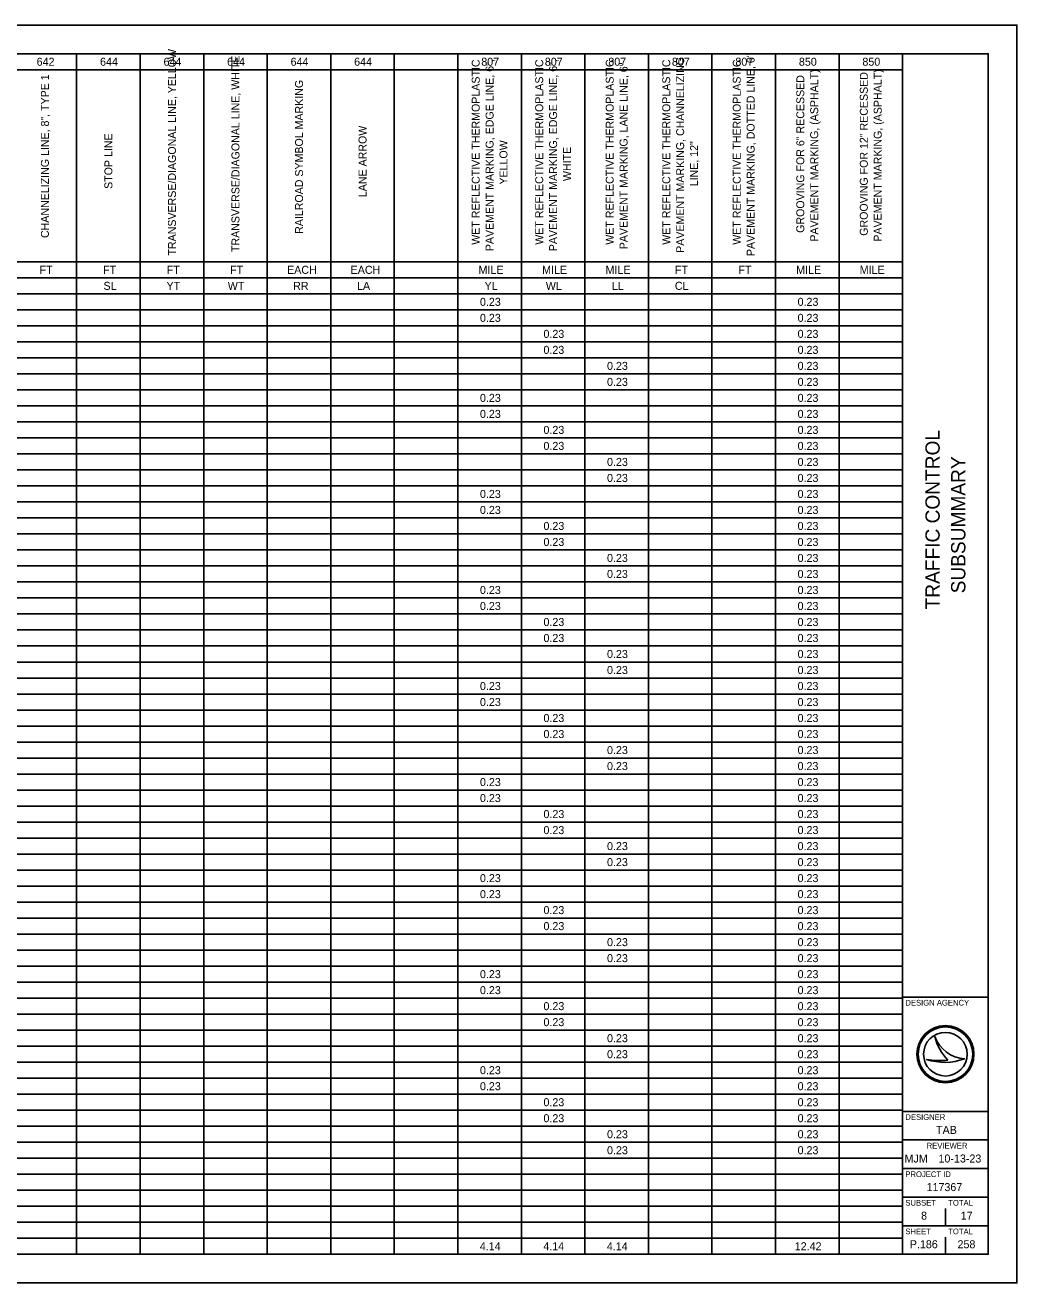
# Model space of a CAD drawing. Extents: x 0 to 34, y 0 to 22.
# Drawn here: x 16.65 to 34, y 0 to 22 of the extents above; entities that cross this region are included whole.
import ezdxf

# ---------------------------------------------------------------- set-up
doc = ezdxf.new("R2010")
doc.units = 0
for name, color, linetype in [('SH_Border', 7, 'Continuous'), ('SH_Cut_Line', 7, 'Continuous'), ('SH_Data', 7, 'Continuous'), ('SH_Text', 7, 'Continuous')]:
    doc.layers.add(name, color=color, linetype=linetype)

msp = doc.modelspace()

# ---------------------------------------------------------------- linework, layer by layer
at = {"layer": 'SH_Border'}
for p, q in [((32, 0.5), (32, 21.5)), ((32, 5), (33.5, 5)), ((32, 3), (33.5, 3)), ((32, 2.5), (33.5, 2.5)), ((32, 2), (33.5, 2)), ((32, 1.5), (33.5, 1.5)), ((32, 1), (33.5, 1))]:
    msp.add_line(p, q, dxfattribs=at)
msp.add_lwpolyline([(1.5, 21.5), (33.5, 21.5), (33.5, 0.5), (1.5, 0.5)], close=True, dxfattribs=at)
at = {"layer": 'SH_Cut_Line'}
msp.add_lwpolyline([(0, 0), (34, 0), (34, 22), (0, 22)], close=True, dxfattribs=at)
at = {"layer": 'SH_Data'}
for p, q in [((32.567, 4.31), (32.567, 4.31)), ((32.75, 4), (32.75, 4)), ((32.417, 3.91), (32.417, 3.91)), ((33.087, 3.919), (33.087, 3.919)), ((32.75, 1), (32.75, 1.3)), ((32.375, 0.675), (32.375, 0.675)), ((32.75, 0.5), (32.75, 0.8))]:
    msp.add_line(p, q, dxfattribs=at)
for radius in [0.5, 0.477, 0.477, 0.382]:
    msp.add_circle((32.75, 4), radius, dxfattribs=at)
for centre, radius, start, end in [((33.116, 4.498), 0.58, 198.9257, 198.9319), ((33.347, 4.47), 0.796, 191.6379, 191.6421), ((33.116, 4.498), 0.58, 198.9319, 267.1657), ((33.347, 4.47), 0.796, 191.6421, 226.0947), ((32.739, 4.87), 1.013, 251.4576, 290.0832), ((32.648, 5.154), 1.266, 259.4964, 259.4995), ((32.739, 4.87), 1.013, 251.4527, 251.4576), ((32.648, 5.154), 1.266, 259.4995, 276.6672)]:
    msp.add_arc(centre, radius, start, end, dxfattribs=at)
at = {"layer": 'SH_Text'}
for p, q in [((1.5, 21.5), (32, 21.5)), ((17.551, 21.5), (17.551, 0.5)), ((18.662, 21.5), (18.662, 0.5)), ((19.774, 21.5), (19.774, 0.5)), ((20.885, 21.5), (20.885, 0.5)), ((21.997, 21.5), (21.997, 0.5)), ((23.108, 21.5), (23.108, 0.5)), ((24.22, 21.5), (24.22, 0.5)), ((25.331, 21.5), (25.331, 0.5)), ((26.443, 21.5), (26.443, 0.5)), ((27.554, 21.5), (27.554, 0.5)), ((28.666, 21.5), (28.666, 0.5)), ((29.777, 21.5), (29.777, 0.5)), ((30.889, 21.5), (30.889, 0.5)), ((32, 21.5), (32, 0.5)), ((8.659, 21.22), (32, 21.22)), ((8.659, 17.86), (32, 17.86)), ((1.5, 17.58), (32, 17.58)), ((1.5, 17.3), (32, 17.3)), ((1.5, 17.02), (32, 17.02)), ((1.5, 16.74), (32, 16.74)), ((1.5, 16.46), (32, 16.46)), ((1.5, 16.18), (32, 16.18)), ((1.5, 15.9), (32, 15.9)), ((1.5, 15.62), (32, 15.62)), ((1.5, 15.34), (32, 15.34)), ((1.5, 15.06), (32, 15.06)), ((1.5, 14.78), (32, 14.78)), ((1.5, 14.5), (32, 14.5)), ((1.5, 14.22), (32, 14.22)), ((1.5, 13.94), (32, 13.94)), ((1.5, 13.66), (32, 13.66)), ((1.5, 13.38), (32, 13.38)), ((1.5, 13.1), (32, 13.1)), ((1.5, 12.82), (32, 12.82)), ((1.5, 12.54), (32, 12.54)), ((1.5, 12.26), (32, 12.26)), ((1.5, 11.98), (32, 11.98)), ((1.5, 11.7), (32, 11.7)), ((1.5, 11.42), (32, 11.42)), ((1.5, 11.14), (32, 11.14)), ((1.5, 10.86), (32, 10.86)), ((1.5, 10.58), (32, 10.58)), ((1.5, 10.3), (32, 10.3)), ((1.5, 10.02), (32, 10.02)), ((1.5, 9.74), (32, 9.74)), ((1.5, 9.46), (32, 9.46)), ((1.5, 9.18), (32, 9.18)), ((1.5, 8.9), (32, 8.9)), ((1.5, 8.62), (32, 8.62)), ((1.5, 8.34), (32, 8.34)), ((1.5, 8.06), (32, 8.06)), ((1.5, 7.78), (32, 7.78)), ((1.5, 7.5), (32, 7.5)), ((1.5, 7.22), (32, 7.22)), ((1.5, 6.94), (32, 6.94)), ((1.5, 6.66), (32, 6.66)), ((1.5, 6.38), (32, 6.38)), ((1.5, 6.1), (32, 6.1)), ((1.5, 5.82), (32, 5.82)), ((1.5, 5.54), (32, 5.54)), ((1.5, 5.26), (32, 5.26)), ((1.5, 4.98), (32, 4.98)), ((1.5, 4.7), (32, 4.7)), ((1.5, 4.42), (32, 4.42)), ((1.5, 4.14), (32, 4.14)), ((1.5, 3.86), (32, 3.86)), ((1.5, 3.58), (32, 3.58)), ((1.5, 3.3), (32, 3.3)), ((1.5, 3.02), (32, 3.02)), ((1.5, 2.74), (32, 2.74)), ((1.5, 2.46), (32, 2.46)), ((1.5, 2.18), (32, 2.18)), ((1.5, 1.9), (32, 1.9)), ((1.5, 1.62), (32, 1.62)), ((1.5, 1.34), (32, 1.34)), ((1.5, 1.06), (32, 1.06)), ((1.5, 0.78), (32, 0.78)), ((1.5, 0.5), (32, 0.5))]:
    msp.add_line(p, q, dxfattribs=at)

# ---------------------------------------------------------------- texts
at = {"layer": 'SH_Data'}
for s, p in [('TRAFFIC CONTROL', (32.65, 11.78)), ('SUBSUMMARY', (33.1, 12.061))]:
    msp.add_text(s, height=0.25, rotation=90, dxfattribs=at).set_placement(p)
for s, height, p in [('DESIGN AGENCY', 0.1, (32.05, 4.85)), ('DESIGNER', 0.1, (32.05, 2.85)), ('TAB', 0.14, (32.586, 2.605)), ('REVIEWER', 0.1, (32.422, 2.35)), ('MJM', 0.14, (32.035, 2.105)), ('10-13-23', 0.14, (32.629, 2.105)), ('PROJECT ID', 0.1, (32.05, 1.85)), ('117367', 0.14, (32.42, 1.605)), ('SUBSET', 0.1, (32.05, 1.35)), ('TOTAL', 0.1, (32.8, 1.35)), ('8', 0.14, (32.324, 1.105)), ('17', 0.14, (33.018, 1.105)), ('SHEET', 0.1, (32.05, 0.85)), ('TOTAL', 0.1, (32.8, 0.85)), ('P.186', 0.14, (32.127, 0.605)), ('258', 0.14, (32.962, 0.605))]:
    msp.add_text(s, height=height, dxfattribs=at).set_placement(p)
at = {"layer": 'SH_Text'}
for s, height, p in [('TRANSVERSE/DIAGONAL LINE, YELLOW', 0.13893, (19.288, 17.97)), ('TRANSVERSE/DIAGONAL LINE, WHITE', 0.13893, (20.399, 18.031)), ('WET REFLECTIVE THERMOPLASTIC ', 0.13893, (24.602, 18.159)), ('PAVEMENT MARKING, EDGE LINE, 6", ', 0.13893, (24.845, 18.046)), ('WET REFLECTIVE THERMOPLASTIC ', 0.13893, (25.713, 18.159)), ('PAVEMENT MARKING, EDGE LINE, 6", ', 0.13893, (25.956, 18.046)), ('WET REFLECTIVE THERMOPLASTIC ', 0.13893, (26.946, 18.159)), ('WET REFLECTIVE THERMOPLASTIC ', 0.13893, (27.936, 18.159)), ('PAVEMENT MARKING, CHANNELIZING ', 0.13893, (28.179, 18.017)), ('WET REFLECTIVE THERMOPLASTIC ', 0.13893, (29.169, 18.159)), ('PAVEMENT MARKING, DOTTED LINE, 6"', 0.13893, (29.412, 17.96)), ('CHANNELIZING LINE, 8", TYPE 1', 0.13893, (17.065, 18.276)), ('PAVEMENT MARKING, LANE LINE, 6"', 0.13893, (27.189, 18.08)), ('PAVEMENT MARKING, (ASPHALT)', 0.13893, (30.524, 18.213)), ('GROOVING FOR 12" RECESSED ', 0.13893, (31.392, 18.316)), ('PAVEMENT MARKING, (ASPHALT)', 0.13893, (31.635, 18.213)), ('RAILROAD SYMBOL MARKING', 0.13893, (21.511, 18.349)), ('GROOVING FOR 6" RECESSED ', 0.13893, (30.281, 18.367)), ('LANE ARROW', 0.1389, (22.622, 18.992)), ('STOP LINE', 0.1389, (18.176, 19.136)), ('YELLOW', 0.1389, (25.088, 19.212)), ('WHITE', 0.1389, (26.2, 19.273)), ('LINE, 12"', 0.1389, (28.422, 19.181))]:
    msp.add_text(s, height=height, rotation=90, dxfattribs=at).set_placement(p)
for s, p in [('642', (16.851, 21.29)), ('644', (17.96, 21.29)), ('644', (19.071, 21.29)), ('644', (20.183, 21.29)), ('644', (21.294, 21.29)), ('644', (22.406, 21.29)), ('807', (24.63, 21.29)), ('807', (25.742, 21.29)), ('807', (26.853, 21.29)), ('807', (27.965, 21.29)), ('807', (29.076, 21.29)), ('850', (30.187, 21.29)), ('850', (31.298, 21.29)), ('FT', (16.903, 17.65)), ('FT', (18.014, 17.65)), ('FT', (19.126, 17.65)), ('FT', (20.237, 17.65)), ('EACH', (21.232, 17.65)), ('EACH', (22.344, 17.65)), ('MILE', (24.582, 17.65)), ('MILE', (25.694, 17.65)), ('MILE', (26.805, 17.65)), ('FT', (28.017, 17.65)), ('FT', (29.129, 17.65)), ('MILE', (30.139, 17.65)), ('MILE', (31.251, 17.65)), ('SL', (18.021, 17.37)), ('YT', (19.123, 17.37)), ('WT', (20.195, 17.37)), ('RR', (21.338, 17.37)), ('LA', (22.456, 17.37)), ('YL', (24.687, 17.37)), ('WL', (25.759, 17.37)), ('LL', (26.916, 17.37)), ('CL', (28.017, 17.37)), ('0.23', (24.607, 17.09)), ('0.23', (30.164, 17.09)), ('0.23', (24.607, 16.81)), ('0.23', (30.164, 16.81)), ('0.23', (25.718, 16.53)), ('0.23', (30.164, 16.53)), ('0.23', (25.718, 16.25)), ('0.23', (30.164, 16.25)), ('0.23', (26.83, 15.97)), ('0.23', (30.164, 15.97)), ('0.23', (26.83, 15.69)), ('0.23', (30.164, 15.69)), ('0.23', (24.607, 15.41)), ('0.23', (30.164, 15.41)), ('0.23', (24.607, 15.13)), ('0.23', (30.164, 15.13)), ('0.23', (25.718, 14.85)), ('0.23', (30.164, 14.85)), ('0.23', (25.718, 14.57)), ('0.23', (30.164, 14.57)), ('0.23', (26.83, 14.29)), ('0.23', (30.164, 14.29)), ('0.23', (26.83, 14.01)), ('0.23', (30.164, 14.01)), ('0.23', (24.607, 13.73)), ('0.23', (30.164, 13.73)), ('0.23', (24.607, 13.45)), ('0.23', (30.164, 13.45)), ('0.23', (25.718, 13.17)), ('0.23', (30.164, 13.17)), ('0.23', (25.718, 12.89)), ('0.23', (30.164, 12.89)), ('0.23', (26.83, 12.61)), ('0.23', (30.164, 12.61)), ('0.23', (26.83, 12.33)), ('0.23', (30.164, 12.33)), ('0.23', (24.607, 12.05)), ('0.23', (30.164, 12.05)), ('0.23', (24.607, 11.77)), ('0.23', (30.164, 11.77)), ('0.23', (25.718, 11.49)), ('0.23', (30.164, 11.49)), ('0.23', (25.718, 11.21)), ('0.23', (30.164, 11.21)), ('0.23', (26.83, 10.93)), ('0.23', (30.164, 10.93)), ('0.23', (26.83, 10.65)), ('0.23', (30.164, 10.65)), ('0.23', (24.607, 10.37)), ('0.23', (30.164, 10.37)), ('0.23', (24.607, 10.09)), ('0.23', (30.164, 10.09)), ('0.23', (25.718, 9.81)), ('0.23', (30.164, 9.81)), ('0.23', (25.718, 9.53)), ('0.23', (30.164, 9.53)), ('0.23', (26.83, 9.25)), ('0.23', (30.164, 9.25)), ('0.23', (26.83, 8.97)), ('0.23', (30.164, 8.97)), ('0.23', (24.607, 8.69)), ('0.23', (30.164, 8.69)), ('0.23', (24.607, 8.41)), ('0.23', (30.164, 8.41)), ('0.23', (25.718, 8.13)), ('0.23', (30.164, 8.13)), ('0.23', (25.718, 7.85)), ('0.23', (30.164, 7.85)), ('0.23', (26.83, 7.57)), ('0.23', (30.164, 7.57)), ('0.23', (26.83, 7.29)), ('0.23', (30.164, 7.29)), ('0.23', (24.607, 7.01)), ('0.23', (30.164, 7.01)), ('0.23', (24.607, 6.73)), ('0.23', (30.164, 6.73)), ('0.23', (25.718, 6.45)), ('0.23', (30.164, 6.45)), ('0.23', (25.718, 6.17)), ('0.23', (30.164, 6.17)), ('0.23', (26.83, 5.89)), ('0.23', (30.164, 5.89)), ('0.23', (26.83, 5.61)), ('0.23', (30.164, 5.61)), ('0.23', (24.607, 5.33)), ('0.23', (30.164, 5.33)), ('0.23', (24.607, 5.05)), ('0.23', (30.164, 5.05)), ('0.23', (25.718, 4.77)), ('0.23', (30.164, 4.77)), ('0.23', (25.718, 4.49)), ('0.23', (30.164, 4.49)), ('0.23', (26.83, 4.21)), ('0.23', (30.164, 4.21)), ('0.23', (26.83, 3.93)), ('0.23', (30.164, 3.93)), ('0.23', (24.607, 3.65)), ('0.23', (30.164, 3.65)), ('0.23', (24.607, 3.37)), ('0.23', (30.164, 3.37)), ('0.23', (25.718, 3.09)), ('0.23', (30.164, 3.09)), ('0.23', (25.718, 2.81)), ('0.23', (30.164, 2.81)), ('0.23', (26.83, 2.53)), ('0.23', (30.164, 2.53)), ('0.23', (26.83, 2.25)), ('0.23', (30.164, 2.25)), ('4.14', (24.604, 0.57)), ('4.14', (25.715, 0.57)), ('4.14', (26.827, 0.57)), ('12.42', (30.114, 0.57))]:
    msp.add_text(s, height=0.14, dxfattribs=at).set_placement(p)

doc.saveas('drawing.dxf')
